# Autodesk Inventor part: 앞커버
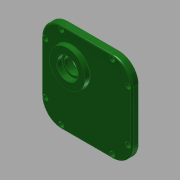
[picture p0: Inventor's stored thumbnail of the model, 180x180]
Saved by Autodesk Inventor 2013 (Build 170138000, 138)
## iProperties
Created: 2016-12
Part Number: 앞커버
Material: 일반
Document SubType Name: Modeling
Designer: mduedu
Density: 1 g/cm^3
Author: mduedu
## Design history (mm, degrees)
sketch "스케치1"
  geometry: L1 (-46, 42)-(-46, -36); L2 (-16, 72)-(62, 72); L3 (92, 42)-(92, -36); L4 (62, -66)-(-16, -66); A1 r 30 centre (-16, -36) between (-46, -36) and (-16, -66); A2 r 30 centre (62, 42) between (92, 42) and (62, 72); A3 r 30 centre (62, -36) between (62, -66) and (92, -36); A4 r 30 centre (-16, 42) between (-16, 72) and (-46, 42); 1 further point
  constraints: 8 end point, 8 point on circle, 8 tangent, 4 centre point, 3 equal radius, 2 perpendicular, 1 horizontal
  dimensions: "d89" = 30 radius of A2; "d90" = 92 distance from line of L3 point (0, 0); "d91" = 138 distance between parallel lines of L4 L2; "d92" = 72 distance from line of point (0, 0) L2; "d114" = 46 distance from line of point (0, 0) L1
extrude "돌출1" new body sketch "스케치1" distance "d3" = 10; taper "d4" = 0 deg
sketch "스케치2"
  geometry: C1 r 21 at (0, 26); 1 further point
  constraints: 1 centre point, 1 vertical alignment
  dimensions: "d5" = 42 diameter of C1; "d7" = 26 distance of C1.centre point (0, 0)
extrude "돌출2" join sketch "스케치2" distance "d8" = 7; taper "d9" = 0 deg
sketch "스케치3"
  geometry: C1 r 15 at (0, -28.87); C2 r 21 at (0, 26) reference; C3 r 15 at (-54.87, 26); 1 further point
  constraints: 2 centre point, 1 horizontal alignment, 1 vertical alignment
  dimensions: "d10" = 30 diameter of C1; "d71" = 54.87 distance of C1.centre C2.centre; "d94" = 30 diameter of C3; "d95" = 54.87 distance of C2.centre C3.centre
extrude "돌출3" join sketch "스케치3" distance "d12" = 7; taper "d13" = 0 deg; dims "d50" = 90 deg
sketch "스케치4"
  geometry: C1 r 21 at (0, 26) reference; C2 r 28 at (0, 26); 1 further point
  constraints: 1 centre point, 1 coincident
  dimensions: "d14" = 56 diameter of C2
extrude "돌출4" join sketch "스케치4" distance "d15" = 7; taper "d16" = -5 deg
hole "구멍1" diameter "d19" = 35; stored, may be unused: countersink angle "d23" = 90 deg, drill point angle "d25" = 0 deg; dims "d17" = 10, "d18" = 10, "d20" = 6, "d21" = 4, "d22" = 2, "d24" = 10
hole "구멍2" diameter "d28" = 22; stored, may be unused: countersink angle "d32" = 90 deg, drill point angle "d34" = 0 deg; dims "d26" = 10, "d27" = 10, "d29" = 6, "d30" = 4, "d31" = 2, "d33" = 7
hole "구멍8" diameter "d98" = 22; stored, may be unused: countersink angle "d102" = 90 deg, drill point angle "d104" = 0 deg; dims "d96" = 10, "d97" = 10, "d99" = 6, "d100" = 4, "d101" = 2, "d103" = 7
hole "구멍3" diameter "d37" = 19; stored, may be unused: countersink angle "d41" = 90 deg, drill point angle "d43" = 0 deg; dims "d35" = 10, "d36" = 10, "d38" = 6, "d39" = 4, "d40" = 2, "d42" = 1
hole "구멍9" diameter "d107" = 19; stored, may be unused: countersink angle "d111" = 90 deg, drill point angle "d113" = 0 deg; dims "d105" = 10, "d106" = 10, "d108" = 6, "d109" = 4, "d110" = 2, "d112" = 1
hole "구멍4" diameter "d46" = 32; stored, may be unused: countersink angle "d50" = 90 deg, drill point angle "d52" = 0 deg; dims "d44" = 10, "d45" = 10, "d47" = 6, "d48" = 4, "d49" = 2, "d51" = 8
hole "구멍5" diameter "d55" = 25; stored, may be unused: countersink angle "d59" = 90 deg, drill point angle "d61" = 0 deg; dims "d53" = 10, "d54" = 10, "d56" = 6, "d57" = 4, "d58" = 2, "d60" = 8
fillet "모깎기1" dims "d62" = 0.3
fillet "모깎기2" dims "d63" = 2
chamfer "모따기1" distance "d64" = 1; stored, may be unused: second distance "d65" = 2, angle "d66" = 45 deg
fillet "모깎기4" dims "d68" = 2
fillet "모깎기5" dims "d69" = 0.3
fillet "모깎기6" dims "d70" = 2
sketch "스케치5"
  geometry: L1 (62, 72)-(-16, 72) reference; L2 (92, -36)-(92, 42) reference; L3 (-16, -66)-(62, -66) reference; L4 (-46, 42)-(-46, -36) reference; L5 (-40, 42)-(-40, -36); L6 (-16, -60)-(62, -60); L7 (86, -36)-(86, 42); L8 (62, 66)-(-16, 66); A1 r 30 centre (62, 42) between (92, 42) and (62, 72) reference; A2 r 30 centre (62, -36) between (62, -66) and (92, -36) reference; A3 r 30 centre (-16, -36) between (-46, -36) and (-16, -66) reference; A4 r 30 centre (-16, 42) between (-16, 72) and (-46, 42) reference; A5 r 24 centre (-16, -36) between (-40, -36) and (-16, -60); A6 r 24 centre (62, -36) between (62, -60) and (86, -36); A7 r 24 centre (62, 42) between (86, 42) and (62, 66); A8 r 24 centre (-16, 42) between (-16, 66) and (-40, 42)
  constraints: 8 end point, 8 point on circle, 4 centre point, 7 other
  dimensions: "d93" = 6 distance between parallel lines of L5 L4
sketch "스케치7"
  geometry: L1 (62, 66)-(-16, 66) reference; L2 (86, -36)-(86, 42) reference; L3 (-16, -60)-(62, -60) reference; L4 (-40, 42)-(-40, -36) reference; A1 r 24 centre (62, 42) between (86, 42) and (62, 66) reference; A2 r 24 centre (62, -36) between (62, -60) and (86, -36) reference; A3 r 24 centre (-16, -36) between (-40, -36) and (-16, -60) reference; A4 r 24 centre (-16, 42) between (-16, 66) and (-40, 42) reference; 8 further points
  constraints: 8 coincident
hole "구멍7" sketch "스케치7" at (-40, 42), (-40, -36), (-16, -60), (62, -60), (86, -36), (86, 42), (62, 66), (-16, 66) diameter "d80" = 4.5; stored, may be unused: countersink angle "d84" = 90 deg, drill point angle "d86" = 0 deg; dims "d81" = 6, "d82" = 8, "d83" = 4.6, "d85" = 8
node "솔리드1"
